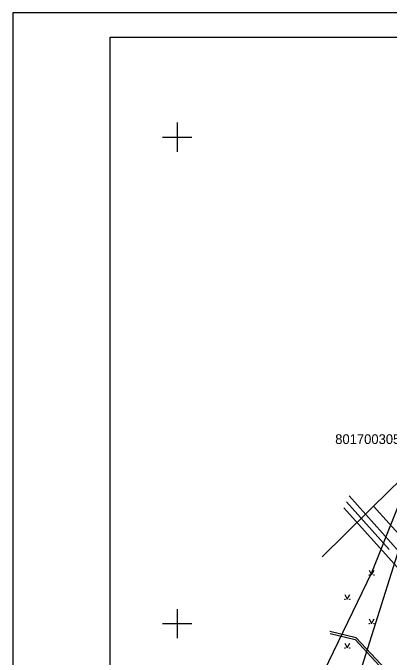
# Model space of a CAD drawing. Extents: x 532933 to 533143, y 328014 to 328163.
# Drawn here: x 532933.1 to 532971.8, y 328096.6 to 328162.8 of the extents above; entities that cross this region are included whole.
import ezdxf

# ---------------------------------------------------------------- set-up
doc = ezdxf.new("R2010")
doc.units = 0
for name, color, linetype in [('DREN_VADP_####_####_#', 7, 'Continuous'), ('ELEK_VADP_ZSPR_####_#', 7, 'Continuous'), ('GEOD_ELEM_####_####_#', 7, 'Continuous'), ('NORB_ZOGS_ZSTP_####_#', 7, 'Continuous'), ('RAMI_PLAN_####_TKST_#', 7, 'Continuous'), ('RAMI_UZMR_####_####_#', 7, 'Continuous'), ('ROBZ_UZMR_####_####_#', 7, 'Continuous'), ('ROBZ_UZMR_####_TKST_#', 7, 'Continuous'), ('SILT_VADP_NEDR_####_#', 7, 'Continuous'), ('SILT_VADP_UDEN_TKAM_#', 7, 'Continuous'), ('TERT_ELEM_####_####_#', 7, 'Continuous')]:
    doc.layers.add(name, color=color, linetype=linetype)

msp = doc.modelspace()

# ---------------------------------------------------------------- linework, layer by layer
at = {"layer": 'DREN_VADP_####_####_#'}
msp.add_line((532992.538, 328087.211), (532970.198, 328112.068), dxfattribs=at)
at = {"layer": 'ELEK_VADP_ZSPR_####_#'}
for points in [[(532985.737, 328079.805), (532977.556, 328088.778), (532968.408, 328098.547), (532965.686, 328099.193)], [(532965.739, 328098.982), (532968.304, 328098.364), (532985.598, 328079.659)]]:
    msp.add_lwpolyline(points, dxfattribs=at)
at = {"layer": 'GEOD_ELEM_####_####_#'}
for p, q in [((532950, 328151.5), (532950, 328150)), ((532948.5, 328150), (532950, 328150)), ((532950, 328150), (532950, 328148.5)), ((532950, 328150), (532951.5, 328150)), ((532950, 328101.5), (532950, 328100)), ((532948.5, 328100), (532950, 328100)), ((532950, 328100), (532950, 328098.5)), ((532950, 328100), (532951.5, 328100))]:
    msp.add_line(p, q, dxfattribs=at)
at = {"layer": 'NORB_ZOGS_ZSTP_####_#'}
msp.add_lwpolyline([(532975.922, 328117.541), (532972.059, 328113.9), (532964.921, 328106.875)], dxfattribs=at)
at = {"layer": 'RAMI_PLAN_####_TKST_#'}
for p, q in [((533143.097, 328162.773), (532933.097, 328162.773)), ((532933.097, 328162.773), (532933.097, 328014.273)), ((532943.097, 328160.273), (533140.597, 328160.273)), ((532943.097, 328016.773), (532943.097, 328160.273))]:
    msp.add_line(p, q, dxfattribs=at)
at = {"layer": 'RAMI_UZMR_####_####_#'}
msp.add_lwpolyline([(532947.854, 328059.458), (532970.012, 328105.269), (532980.164, 328130.66), (532983.041, 328140.509), (533003.397, 328153.917), (533034.71, 328122.623), (533045.001, 328112.629), (533020.332, 328088.009), (533039.378, 328069.977), (533029.682, 328029.753), (533016.724, 328021.343), (532947.854, 328059.458)], dxfattribs=at)
at = {"layer": 'ROBZ_UZMR_####_####_#'}
msp.add_line((532984.275, 328144.093), (532962.791, 328075.982), dxfattribs=at)
at = {"layer": 'SILT_VADP_NEDR_####_#'}
msp.add_line((532971.8, 328107.627), (532967.413, 328112.519), dxfattribs=at)
at = {"layer": 'SILT_VADP_UDEN_TKAM_#'}
for p, q in [((532972.841, 328107.364), (532967.679, 328113.121)), ((532971.734, 328106.801), (532967.147, 328111.916))]:
    msp.add_line(p, q, dxfattribs=at)
msp.add_lwpolyline([(532988.353, 328088.27), (532971.734, 328106.801)], dxfattribs=at)
at = {"layer": 'TERT_ELEM_####_####_#'}
for p, q in [((532969.75, 328105.5), (532970, 328105)), ((532970, 328105), (532970.25, 328105.5)), ((532967.25, 328103), (532967.5, 328102.5)), ((532967.5, 328102.5), (532967.75, 328103)), ((532969.75, 328100.5), (532970, 328100)), ((532970, 328100), (532970.25, 328100.5)), ((532967.25, 328098), (532967.5, 328097.5)), ((532967.5, 328097.5), (532967.75, 328098))]:
    msp.add_line(p, q, dxfattribs=at)
for centre, radius in [((532969.75, 328105), 0.028), ((532970.25, 328105), 0.0263), ((532967.25, 328102.5), 0.028), ((532967.75, 328102.5), 0.0263), ((532969.75, 328100), 0.028), ((532970.25, 328100), 0.0263), ((532967.25, 328097.5), 0.028), ((532967.75, 328097.5), 0.0263)]:
    msp.add_circle(centre, radius, dxfattribs=at)

# ---------------------------------------------------------------- texts
at = {"layer": 'ROBZ_UZMR_####_TKST_#'}
msp.add_text('80170030501', height=1, dxfattribs=at).set_placement((532966.254, 328118.463))

doc.saveas('drawing.dxf')
